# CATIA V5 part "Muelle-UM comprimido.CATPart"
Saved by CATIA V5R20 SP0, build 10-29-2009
Part number: Muelle-UM comprimido
Revision: ANY
Definition: UNKNOWN
Nomenclature: Muelle-UM comprimido
Source: Unknown
Bounding box of the stored display mesh (mm): x -1.2 to 1.2, y -1.2 to 1.2, z -0.001 to 4
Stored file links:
  C:\Users\Utente\Desktop\IO LAVORO\3D X SITO CF\X SITO\3D files UM\UM064242 PRODUCT\Muelle-UM comprimido.CATPart
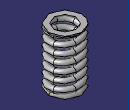
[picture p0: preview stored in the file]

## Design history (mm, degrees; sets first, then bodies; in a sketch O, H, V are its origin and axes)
Body1 "Cortar-Extruir1" (main body)
  Solid1: solid without history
